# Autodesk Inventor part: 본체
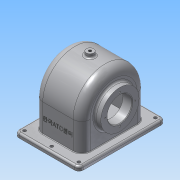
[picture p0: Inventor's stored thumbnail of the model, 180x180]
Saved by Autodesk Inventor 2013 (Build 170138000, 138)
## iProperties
Created: 2015-09
Part Number: 본체
Material: 알루미늄 6061
Document SubType Name: Modeling
Designer: ST3
Density: 2.71 g/cm^3
Mass: 867.365 g
Surface Area: 976.163 cm^2
Volume: 320.061 cm^3
Author: ST3
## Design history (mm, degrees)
sketch "스케치2"
  geometry: L1 (-52, 70)-(52, 70); L2 (52, 70)-(52, -70); L3 (52, -70)-(-52, -70); L4 (-52, -70)-(-52, 70); 1 further point
  constraints: 8 end point, 2 parallel, 1 horizontal, 1 perpendicular
  dimensions: "d0" = 104 distance of L1.start L1.end; "d2" = 140 distance of L1.end L2.end; "d6" = 70 distance from line of point (0, 0) L1; "d7" = 52 distance from line of L4 point (0, 0)
extrude "돌출1" new body sketch "스케치2" distance "d3" = 7; taper "d4" = 0 deg
node "작업 평면2"
sketch "스케치4"
  geometry: L1 (-62.25, 0)-(65.77, 0); L2 (48.5, 20)-(48.5, 31); L3 (48.5, 31)-(38.5, 31); L4 (38.5, 31)-(38.5, 52); L5 (38.5, 52)-(-38.5, 52); L6 (-38.5, 52)-(-38.5, 35.101); L7 (-38.5, 35.101)-(-35.5, 33); L8 (-35.5, 33)-(-35.5, 20); L9 (-35.5, 20)-(-19.5, 20); L10 (-19.5, 20)-(-19.5, 28); L11 (-19.5, 28)-(-33.5, 39.747); L12 (-33.5, 39.747)-(-33.5, 46); L13 (-33.5, 46)-(33.5, 46); L14 (33.5, 46)-(33.5, 20); L15 (33.5, 20)-(48.5, 20); 1 further point
  constraints: 30 end point, 7 parallel, 5 perpendicular, 1 horizontal
  dimensions: "d9" = 0 distance from line of point (0, 0) L1; "d10" = 16 distance between parallel lines of L8 L10; "d12" = 56 diameter of L10.end L1; "d13" = 40 diameter of L15 L1; "d14" = 62 diameter of L3 L1; "d17" = 40 diameter of L9 L1; "d18" = 66 diameter of L7.end L1; "d19" = 50 deg angle of L11 L10; "d21" = 104 diameter of L5 L1; "d25" = 3 distance between parallel lines of L8 L6; "d26" = 5 deg angle of L7 L11; "d27" = 5 distance between parallel lines of L12 L6; "d28" = 67 distance between parallel lines of L12 L14; "d29" = 5 distance between parallel lines of L14 L4; "d30" = 10 distance between parallel lines of L4 L2; "d31" = 38.5 distance from line of point (0, 0) L6; "d34" = 6 distance between parallel lines of L13 L5
revolve "회전1" sketch "스케치4" stored, may be unused: angle "d35" = 90 deg
sketch "스케치7"
  geometry: L1 (45, -70)-(45, 70) reference; L2 (45, -52)-(45, -26.058); L3 (45, 26.058)-(45, 52); L4 (0, -52)-(45, -52); L5 (45, 52)-(0, 52); A1 r 52 centre (0, 0) between (45, 26.058) and (45, -26.058) reference; A2 r 52 centre (0, 0) between (0, -52) and (45, -26.058); A3 r 52 centre (0, 0) between (45, 26.058) and (0, 52); 1 further point
  constraints: 8 end point, 6 point on circle, 3 tangent, 2 centre point, 2 collinear, 2 concentric, 2 point on line, 1 parallel, 1 perpendicular
extrude "돌출3" join sketch "스케치7" stored distance "d38" = 7; taper "d39" = 0 deg
sketch "스케치8"
  geometry: L1 (9.539, 7)-(-9.539, 7) reference; L2 (-52, 7)-(52, 7) reference; L3 (-46, 52)-(-46, 7); L4 (46, 52)-(46, 7); L5 (-46, 7)-(46, 7); A1 r 46 centre (0, 52) between (9.539, 7) and (-9.539, 7) reference; A2 r 46 centre (0, 52) between (-46, 52) and (-9.539, 7); A3 r 46 centre (0, 52) between (9.539, 7) and (46, 52); 1 further point
  constraints: 6 end point, 6 point on circle, 2 centre point, 2 concentric, 2 perpendicular, 2 point on line, 2 tangent, 1 collinear
extrude "돌출4" cut sketch "스케치8" stored distance "d40" = 7; taper "d41" = 0 deg
sketch "스케치9"
  geometry: 1 further point
sketch "스케치10"
  geometry: L1 (-52, 7)-(52, 7) reference; L2 (-46, 52)-(-46, 7); L3 (46, 52)-(46, 7); L4 (-46, 7)-(-9.539, 7); L5 (9.539, 7)-(46, 7); A1 r 46 centre (0, 52) between (9.539, 7) and (-9.539, 7) reference; A2 r 46 centre (0, 52) between (-46, 52) and (-9.539, 7); A3 r 46 centre (0, 52) between (9.539, 7) and (46, 52); 1 further point
  constraints: 8 end point, 6 point on circle, 2 centre point, 2 collinear, 2 concentric, 2 perpendicular, 2 point on line, 2 tangent
extrude "돌출5" cut sketch "스케치10" stored distance "d42" = 7; taper "d43" = 0 deg
node "작업 평면4"
sketch "스케치11"
  geometry: C1 r 6 at (0, 0); 1 further point
  constraints: 1 centre point, 1 coincident
  dimensions: "d45" = 12 diameter of C1
extrude "돌출6" join sketch "스케치11" stored distance "d47" = 7; taper "d48" = 0 deg
sketch "스케치12"
  geometry: 1 further point
sketch "스케치15"
  geometry: C1 r 6 at (0, 0) reference
hole "구멍1" sketch "스케치15" at (0, 0) diameter "d50" = 4.459; stored, may be unused: countersink angle "d54" = 90 deg, drill point angle "d56" = 0 deg; dims "d51" = 20, "d52" = 4, "d53" = 2, "d55" = 8
fillet "모깎기1" dims "d61" = 3
fillet "모깎기3" dims "d63" = 14
fillet "모깎기4" dims "d64" = 9
fillet "모깎기5" dims "d65" = 1
sketch "스케치18"
  geometry: L1 (15.579, -20.03)-(33.421, -20.03); L2 (33.421, -20.03)-(33.421, -23.97); L3 (33.421, -23.97)-(15.579, -23.97); L4 (15.579, -23.97)-(15.579, -20.03); L5 (15.579, -22)-(33.421, -22); L6 (24.5, -23.97)-(24.5, -20.03); L7 (-14, 0)-(-14, -44) reference; L8 (76.5, -52)-(-27.5, -52) reference; 3 further points
  constraints: 4 end point, 4 midpoint, 2 other
  dimensions: "d66" = 38.5 distance between parallel lines of L6 L7; "d67" = 30 distance between parallel lines of L5 L8
extrude "돌출7" join sketch "스케치18" distance "d68" = 0.5; taper "d69" = 0 deg
fillet "모깎기6" dims "d70" = 3
chamfer "모따기1" distance "d71" = 1; stored, may be unused: second distance "d72" = 2, angle "d73" = 45 deg
sketch "스케치19" dims "d74" = 48
  geometry: C1 r 31 at (0, 0) reference; C2 r 21 at (0, 0) reference; 3 further points
  constraints: 1 coincident, 1 horizontal alignment, 2 other
  dimensions: "d76" = 0 vertical distance of point (-24, 0) C1.centre
hole "구멍2" sketch "스케치19" at (-24, 0) diameter "d77" = 2.459; stored, may be unused: countersink angle "d81" = 90 deg, drill point angle "d83" = 118 deg; dims "d78" = 6, "d79" = 4, "d80" = 2, "d82" = 8
sketch "스케치20" dims "d87" = 56
  geometry: C1 r 33 at (0, 0) reference; C2 r 21 at (0, 0) reference; 3 further points
  constraints: 1 coincident, 1 horizontal alignment, 2 other
  dimensions: "d89" = 0 vertical distance of point (28, 0) C1.centre
hole "구멍3" sketch "스케치20" at (28, 0) diameter "d90" = 2.459; stored, may be unused: countersink angle "d94" = 90 deg, drill point angle "d96" = 118 deg; dims "d91" = 7, "d92" = 4, "d93" = 2, "d95" = 9
fillet "모깎기7" dims "d116" = 3
fillet "모깎기8" dims "d117" = 7
fillet "모깎기9" dims "d118" = 7
sketch "스케치26"
  geometry: L1 (-52, 63)-(-52, -63) reference; L2 (45, 70)-(-45, 70) reference; L3 (-45, -70)-(45, -70) reference; C1 r 2.5 at (-44, 62); C2 r 2.5 at (0, 62); C3 r 2.5 at (44, 62); C4 r 2.5 at (0, -62); C5 r 2.5 at (44, -62); C6 r 2.5 at (-44, -62); 1 further point
  constraints: 6 centre point
  dimensions: "d134" = 5 diameter of C1; "d136" = 5 diameter of C2; "d137" = 5 diameter of C3; "d138" = 5 diameter of C5; "d139" = 5 diameter of C4; "d141" = 8 distance from line of C1.centre L1; "d142" = 5 diameter of C6; "d143" = 8 distance from line of L1 C6.centre; "d144" = 44 distance of C4.centre C6.centre; "d145" = 44 distance of C5.centre C4.centre; "d146" = 44 distance of C2.centre C1.centre; "d147" = 44 distance of C3.centre C2.centre; "d148" = 124 distance of C5.centre C3.centre; "d149" = 8 distance from line of C3.centre L2; "d150" = 8 distance from line of C2.centre L2; "d151" = 8 distance from line of C1.centre L2; "d152" = 8 distance from line of C6.centre L3; "d153" = 8 distance from line of L3 C4.centre
extrude "돌출11" cut sketch "스케치26" stored distance "d154" = 0.5; taper "d155" = 0 deg
node "솔리드1"
pattern_circular "원형 패턴1" dims angle "d85" = 360 deg
pattern_circular "원형 패턴2" dims angle "d98" = 360 deg
other parameters: "d8" = 52
